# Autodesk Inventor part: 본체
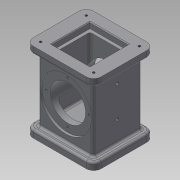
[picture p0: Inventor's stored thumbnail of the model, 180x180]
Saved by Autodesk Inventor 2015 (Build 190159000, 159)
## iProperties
Created: 2017-08
Part Number: 본체
Material: 일반
Document SubType Name: Modeling
Designer: Administrator
Density: 1 g/cm^3
Appearance: 기본값
Author: Administrator
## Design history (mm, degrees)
sketch "스케치1"
  geometry: L1 (37, -33)-(-37, -33); L2 (-37, -33)-(-37, 33); L3 (-37, 33)-(37, 33); L4 (37, 33)-(37, -33); L5 (37, -33)-(-37, 33); L6 (-37, -33)-(37, 33); 1 further point
  constraints: 12 end point, 2 midpoint, 2 parallel, 1 horizontal, 1 perpendicular
  dimensions: "d0" = 74 distance of L1.start L1.end; "d1" = 66 distance of L1.end L2.end
extrude "돌출1" new body sketch "스케치1" stored distance "d2" = 108; taper "d3" = 0 deg
sketch "스케치2"
  geometry: L1 (-46, -41)-(46, -41); L2 (46, -41)-(46, 41); L3 (46, 41)-(-46, 41); L4 (-46, 41)-(-46, -41); L5 (-46, -41)-(46, 41); L6 (46, -41)-(-46, 41); 1 further point
  constraints: 12 end point, 2 midpoint, 2 parallel, 1 horizontal, 1 perpendicular
  dimensions: "d4" = 92 distance of L2.end L3.end; "d5" = 82 distance of L1.end L2.end
extrude "돌출2" join sketch "스케치2" distance "d6" = 10; taper "d7" = 0 deg
fillet "모깎기1" dims "d8" = 10
fillet "모깎기2" dims "d9" = 10
fillet "모깎기3" dims "d10" = 3
sketch "스케치3"
  geometry: L1 (24, 24)-(-24, 24); L2 (-24, 24)-(-24, -24); L3 (-24, -24)-(24, -24); L4 (24, -24)-(24, 24); L5 (24, 24)-(-24, -24); L6 (-24, 24)-(24, -24); 1 further point
  constraints: 12 end point, 2 midpoint, 2 parallel, 1 horizontal, 1 perpendicular
  dimensions: "d12" = 48 distance of L2.end L3.end; "d13" = 48 distance of L3.end L1.start
extrude "돌출3" cut sketch "스케치3" distance "d14" = 16; taper "d15" = 0 deg
fillet "모깎기5" dims "d16" = 3
fillet "모깎기6" dims "d17" = 3
sketch "스케치4"
  geometry: L1 (-26, 26)-(26, 26); L2 (26, 26)-(26, -26); L3 (26, -26)-(-26, -26); L4 (-26, -26)-(-26, 26); L5 (-26, 26)-(26, -26); L6 (26, 26)-(-26, -26); 1 further point
  constraints: 12 end point, 2 midpoint, 2 parallel, 1 horizontal, 1 perpendicular
  dimensions: "d18" = 52 distance of L1.end L2.end; "d19" = 52 distance of L2.end L3.end
extrude "돌출4" cut sketch "스케치4" distance "d20" = 8; taper "d21" = 0 deg
sketch "스케치9"
  geometry: L1 (-22, -22)-(22, -22); L2 (22, -22)-(22, 22); L3 (22, 22)-(-22, 22); L4 (-22, 22)-(-22, -22); L5 (-22, -22)-(22, 22); L6 (22, -22)-(-22, 22); 1 further point
  constraints: 12 end point, 2 midpoint, 2 parallel, 1 horizontal, 1 perpendicular
  dimensions: "d35" = 44 distance of L2.end L3.end; "d36" = 44 distance of L3.end L1.start
extrude "돌출9" cut sketch "스케치9" distance "d37" = 74; taper "d38" = 0 deg
fillet "모깎기7" dims "d39" = 3
fillet "모깎기9" dims "d41" = 3
chamfer "모따기1" distance "d42" = 1; stored, may be unused: second distance "d43" = 2, angle "d44" = 45 deg
fillet "모깎기10" dims "d45" = 3
sketch "스케치10"
  geometry: C1 r 35 at (34, -41); 1 further point
  constraints: 1 centre point, 1 coincident
  dimensions: "d46" = 70 diameter of C1
extrude "돌출10" cut sketch "스케치10" distance "d47" = 3; taper "d48" = 0 deg
sketch "스케치11"
  geometry: C1 r 35 at (34, -41); 1 further point
  constraints: 1 centre point, 1 coincident
  dimensions: "d49" = 70 diameter of C1
extrude "돌출11" cut sketch "스케치11" distance "d50" = 3; taper "d51" = 0 deg
sketch "스케치12"
  geometry: C1 r 24 at (0, 0); 1 further point
  constraints: 1 centre point, 1 coincident
  dimensions: "d52" = 48 diameter of C1
extrude "돌출12" cut sketch "스케치12" stored distance "d53" = 123.5; taper "d54" = 0 deg
sketch "스케치13"
  geometry: L1 (46, -31)-(46, 31) reference; L2 (36, 41)-(-36, 41) reference; L3 (-46, 31)-(-46, -31) reference; L4 (-36, -41)-(36, -41) reference; L5 (-27, 27)-(-27, -27) reference; L6 (27, 27)-(-27, 27) reference; L7 (27, -27)-(27, 27) reference; L8 (-27, -27)-(27, -27) reference; A1 r 10 centre (36, -31) between (36, -41) and (46, -31) reference; A2 r 10 centre (36, 31) between (46, 31) and (36, 41) reference; A3 r 10 centre (-36, 31) between (-36, 41) and (-46, 31) reference; A4 r 10 centre (-36, -31) between (-46, -31) and (-36, -41) reference; 2 further points
  constraints: 1 coincident
hole "구멍1" sketch "스케치13" at (-36, 31) diameter "d55" = 3.242; stored, may be unused: countersink angle "d59" = 90 deg, drill point angle "d61" = 118 deg; dims "d56" = 4, "d57" = 4, "d58" = 2, "d60" = 6
sketch "스케치14" dims "d68" = 58
  geometry: 3 further points
  constraints: 2 vertical alignment, 1 coincident, 2 other
hole "구멍2" sketch "스케치14" at (0, 29) diameter "d69" = 3.242; stored, may be unused: countersink angle "d73" = 90 deg, drill point angle "d75" = 118 deg; dims "d70" = 4, "d71" = 4, "d72" = 2, "d74" = 6
sketch "스케치15"
  geometry: L1 (30, 104.477)-(30, 41); L2 (71, -13)-(61, -13) reference; 2 further points
  constraints: 2 end point, 1 point on line, 1 vertical, 1 vertical alignment
  dimensions: "d79" = 38 distance from line of L2 point (30, 25); "d80" = 42 distance of point (30, 67) point (30, 25)
hole "구멍3" sketch "스케치15" at (30, 67), (30, 25) diameter "d81" = 4.134; stored, may be unused: countersink angle "d85" = 90 deg, drill point angle "d87" = 118 deg; dims "d82" = 36.7, "d83" = 4, "d84" = 2, "d86" = 36.7
node "솔리드1"
mirror "대칭1"
pattern_linear "직사각형 패턴1" dims "d64" = 62, "d67" = 72
mirror "대칭2"
pattern_circular "원형 패턴1" dims angle "d77" = 360 deg
mirror "대칭3"
node "투영된 루프1"
